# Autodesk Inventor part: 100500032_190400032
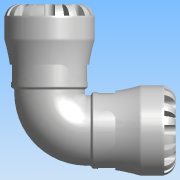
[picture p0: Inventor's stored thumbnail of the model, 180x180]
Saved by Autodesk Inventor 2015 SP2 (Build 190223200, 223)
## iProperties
Created: 2016-12
Part Number: 100500032_190400032
Material: PVC-Piping
Description: PLASSON 90° ELBOW 32X32 SERIES 1
Document SubType Name: Modeling
Designer: KIM
Mass: 664.223 g
Surface Area: 733.008 cm^2
Volume: 474.445 cm^3
Density: 1.4 g/cm^3
Appearance: Smooth - White
Author: KIM
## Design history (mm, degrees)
derived "1005.ipt"
feature "Solid1::1005.ipt"
tag "TaggingFeature1"
body "Solid1"
other parameters: "d1" = 22.68, "d2" = 32, "d4" = 58, "d8" = 49.3, "d13" = 7.2, "d14" = 7.2, "d15" = 0, "d17" = 360 deg, "d19" = 8 deg, "d20" = 0.64, "d21" = 0.64, "d22" = 8 deg, "d24" = 0, "d26" = 360 deg, "d33" = 5.8, "d43" = 45.24, "d51" = 0.58, "d54" = 11.2, "d55" = 7.04, "d57" = 14.112, "d58" = 0, "d74" = 0, "d77" = 2.66667, "d78" = 54, "d82" = 0.64, "d115" = 360 deg, "d207" = 90 deg, "d228" = 9.52, "d247" = 1.16, "d248" = 3.24, "d268" = 27.115, "d269" = 3.24, "d270" = 81, "d272" = 90 deg, "d274" = 0, "d275" = 0, "d_" = 32, "E_" = 58, "l_" = 54, "A_" = 81, "d9" = 9, "d11" = 58
